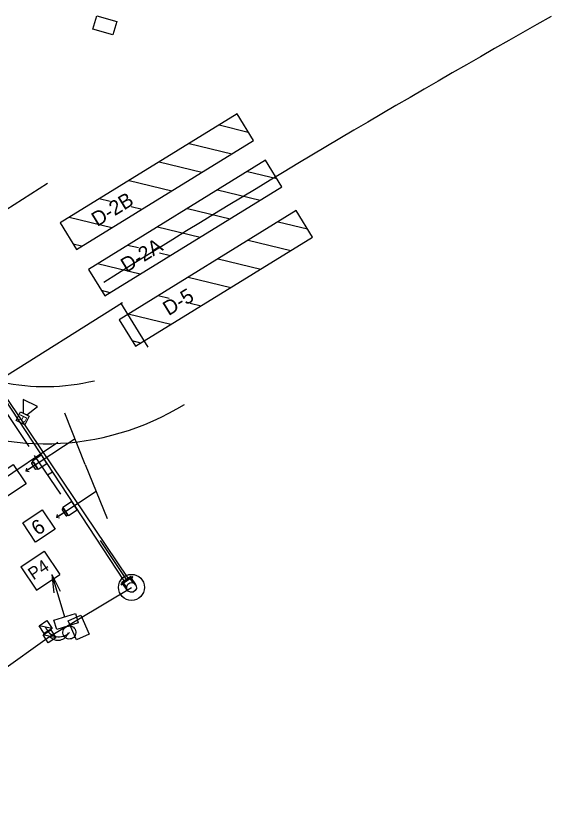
# Model space of a CAD drawing. Extents: x 509004 to 509991, y 882089 to 882397.
# Drawn here: x 509218 to 509321, y 882237.9 to 882390.2 of the extents above; entities that cross this region are included whole.
import ezdxf

# ---------------------------------------------------------------- set-up
doc = ezdxf.new("R2010")
doc.units = 0
for name, color, linetype in [('CLConst_dp', 7, 'Continuous'), ('ConstLines', 7, 'Continuous'), ('TextAlgnCurveData', 7, 'Continuous'), ('TextAlgnStation100', 7, 'Continuous'), ('TextAlgnStation1000', 7, 'Continuous'), ('TextAlgnStation500', 7, 'Continuous'), ('TextAlgnTangent', 7, 'Continuous'), ('TextAlgnTicks1000', 7, 'Continuous'), ('TextAlgnTicks500', 7, 'Continuous'), ('TextAlgnTicks5000', 7, 'Continuous')]:
    doc.layers.add(name, color=color, linetype=linetype)

msp = doc.modelspace()

# ---------------------------------------------------------------- linework, layer by layer
at = {"layer": 'CLConst_dp'}
for p, q in [((509238.84, 882281.59), (509211.35, 882323.35)), ((509239.6, 882282.09), (509211.62, 882323.54)), ((509238.21, 882280.95), (509240.41, 882282.45)), ((509240.09, 882282.42), (509238.35, 882281.26)), ((509240.18, 882282.28), (509238.45, 882281.12)), ((509238.72, 882281.19), (509240, 882282.07)), ((509240.61, 882281.18), (509240, 882282.07)), ((509240.05, 882282), (509240.51, 882282.31)), ((509240.18, 882282.28), (509240.09, 882282.42)), ((509241, 882280.86), (509240.17, 882282.08)), ((509241.05, 882280.89), (509240.22, 882282.11)), ((509240.51, 882282.31), (509240.41, 882282.45)), ((509238.31, 882280.81), (509238.21, 882280.95)), ((509238.31, 882280.81), (509238.77, 882281.12)), ((509238.45, 882281.12), (509238.35, 882281.26)), ((509239.43, 882279.79), (509238.6, 882281.01)), ((509239.48, 882279.82), (509238.65, 882281.04)), ((509239.32, 882280.31), (509238.72, 882281.19)), ((509241.05, 882280.89), (509241, 882280.86)), ((509239.43, 882279.79), (509239.48, 882279.82))]:
    msp.add_line(p, q, dxfattribs=at)
msp.add_lwpolyline([(509239.52, 882280.96), (509239.93, 882281.24), (509240.42, 882281.27), (509240.86, 882281.06), (509241.14, 882280.65), (509241.18, 882280.16), (509240.96, 882279.72), (509240.56, 882279.44), (509240.07, 882279.4), (509239.62, 882279.62), (509239.34, 882280.02), (509239.31, 882280.51)], close=True, dxfattribs=at)
msp.add_circle((509240.24, 882280.35), 2.5, dxfattribs=at)
at = {"layer": 'ConstLines'}
for p, q in [((509224.06, 882358.02), (509191.98, 882337.43)), ((509238.53, 882335.06), (509130.35, 882267.1)), ((509243.47, 882326.52), (509238.21, 882335.06)), ((509220.55, 882307.45), (509215.3, 882315.34)), ((509231.35, 882303.96), (509227.42, 882313.82)), ((509229.38, 882308.89), (509220.24, 882302.89)), ((509121.5, 882237.9), (509226.04, 882308.24)), ((509226.61, 882298.24), (509221.58, 882305.72)), ((509231.35, 882303.96), (509235.58, 882293.58)), ((509224.09, 882301.98), (509225, 882302.59)), ((509233.46, 882298.77), (509226.25, 882294.04))]:
    msp.add_line(p, q, dxfattribs=at)
msp.add_lwpolyline([(509236.65, 882386.57), (509232.81, 882387.67), (509233.54, 882390.24), (509237.39, 882389.13)], close=True, dxfattribs=at)
for centre, radius, start, end in [((510394.49, 880483.77), 2187.81, 119.38433, 122.00756), ((509223.67, 882358.96), 51, 180.6251, 301.6373), ((509223.67, 882358.96), 40, 180.6251, 283.6453)]:
    msp.add_arc(centre, radius, start, end, dxfattribs=at)
at = {"layer": 'TextAlgnCurveData'}
for p, q in [((509224.45, 882270.93), (509240.24, 882280.35)), ((509214.71, 882263.99), (509224.45, 882270.93))]:
    msp.add_line(p, q, dxfattribs=at)
for centre, radius, start, end in [((509226.32, 882273.61), 2.76, 198.7287, 315.3272), ((509226.07, 882272.29), 2.11, 220.2087, 342.3068)]:
    msp.add_arc(centre, radius, start, end, dxfattribs=at)
at = {"layer": 'TextAlgnStation100'}
for p, q in [((509222.47, 882272.98), (509223.97, 882273.97)), ((509223.97, 882273.97), (509224.95, 882272.47)), ((509223.45, 882271.48), (509222.47, 882272.98)), ((509224.95, 882272.47), (509222.47, 882272.98)), ((509224.95, 882272.47), (509223.45, 882271.48)), ((509223.21, 882271.19), (509224.71, 882272.17)), ((509224.19, 882269.69), (509223.21, 882271.19)), ((509225.69, 882270.67), (509223.21, 882271.19)), ((509224.71, 882272.17), (509225.69, 882270.67)), ((509225.69, 882270.67), (509224.19, 882269.69))]:
    msp.add_line(p, q, dxfattribs=at)
at = {"layer": 'TextAlgnStation1000'}
for p, q in [((509221.35, 882304.41), (509222.07, 882303.32)), ((509221.36, 882303.63), (509219.92, 882302.69)), ((509220.05, 882303.28), (509219.92, 882302.69)), ((509221, 882304.18), (509221.72, 882303.09)), ((509221, 882304.18), (509221.72, 882303.09)), ((509220.51, 882302.57), (509219.92, 882302.69)), ((509226.88, 882295.24), (509227.6, 882294.14)), ((509226.88, 882295.24), (509227.6, 882294.14)), ((509227.23, 882295.47), (509227.95, 882294.37)), ((509227.24, 882294.69), (509225.8, 882293.75)), ((509225.93, 882294.34), (509225.8, 882293.75)), ((509226.39, 882293.63), (509225.8, 882293.75))]:
    msp.add_line(p, q, dxfattribs=at)
for points in [[(509222.26, 882303.03), (509221.16, 882304.7), (509222.83, 882305.8), (509223.93, 882304.13)], [(509219.95, 882300.26), (509216.2, 882297.74), (509213.71, 882301.46), (509217.45, 882303.98)], [(509228.14, 882294.09), (509227.04, 882295.76), (509228.71, 882296.85), (509229.81, 882295.18)], [(509225.54, 882291.53), (509221.79, 882289.01), (509219.29, 882292.73), (509223.04, 882295.25)]]:
    msp.add_lwpolyline(points, close=True, dxfattribs=at)
for points in [[(509222.07, 882303.32), (509221.35, 882304.41)], [(509227.95, 882294.37), (509227.23, 882295.47)]]:
    msp.add_lwpolyline(points, dxfattribs=at)
for centre, radius, start, end in [((509221.11, 882304.25), 0.129, 93.9405, 213.2603), ((509221.11, 882304.25), 0.129, 93.9405, 213.2603), ((509220.93, 882306.77), 2.4, 273.9405, 280.0438), ((509220.93, 882306.77), 2.4, 273.9405, 280.0438), ((509221.83, 882303.16), 0.129, 213.2603, 332.5802), ((509221.83, 882303.16), 0.129, 213.2603, 332.5801), ((509224.07, 882301.99), 2.4, 146.4769, 152.5802), ((509224.07, 882301.99), 2.4, 146.4769, 152.5802), ((509226.99, 882295.31), 0.129, 93.9405, 213.2603), ((509226.99, 882295.31), 0.129, 93.9405, 213.2603), ((509226.81, 882297.83), 2.4, 273.9405, 280.0438), ((509226.81, 882297.83), 2.4, 273.9405, 280.0438), ((509227.7, 882294.21), 0.129, 213.2603, 332.5802), ((509227.7, 882294.21), 0.129, 213.2603, 332.5801), ((509229.95, 882293.05), 2.4, 146.4769, 152.5802), ((509229.95, 882293.05), 2.4, 146.4769, 152.5802)]:
    msp.add_arc(centre, radius, start, end, dxfattribs=at)
at = {"layer": 'TextAlgnStation500'}
for p, q in [((509218.96, 882284.32), (509223.44, 882287.33)), ((509223.44, 882287.33), (509226.45, 882282.85)), ((509218.96, 882284.32), (509221.97, 882279.84)), ((509221.97, 882279.84), (509226.45, 882282.85)), ((509224.89, 882282.83), (509227.36, 882274.7)), ((509224.89, 882282.83), (509226.51, 882279.64)), ((509224.89, 882282.83), (509225.32, 882279.27))]:
    msp.add_line(p, q, dxfattribs=at)
at = {"layer": 'TextAlgnTicks1000'}
for p, q in [((509260.56, 882371.4), (509226.5, 882350.42)), ((509263.71, 882366.29), (509260.56, 882371.4)), ((509257.09, 882369.26), (509262.72, 882367.89)), ((509229.65, 882345.31), (509263.71, 882366.29)), ((509251.31, 882365.7), (509259.52, 882363.71)), ((509266.02, 882362.47), (509231.96, 882341.49)), ((509269.16, 882357.36), (509266.02, 882362.47)), ((509245.54, 882362.15), (509253.75, 882360.16)), ((509262.54, 882360.33), (509268.18, 882358.96)), ((509239.77, 882358.59), (509247.98, 882356.6)), ((509235.11, 882336.38), (509269.16, 882357.36)), ((509256.77, 882356.77), (509264.98, 882354.78)), ((509236.14, 882354.53), (509234, 882355.04)), ((509240.17, 882353.57), (509242.27, 882353.08)), ((509251, 882353.22), (509259.21, 882351.23)), ((509271.93, 882352.79), (509237.87, 882331.81)), ((509275.08, 882347.68), (509271.93, 882352.79)), ((509226.5, 882350.42), (509229.65, 882345.31)), ((509236.45, 882349.5), (509228.23, 882351.48)), ((509268.46, 882350.65), (509274.09, 882349.29)), ((509245.23, 882349.66), (509253.44, 882347.67)), ((509241.02, 882326.7), (509275.08, 882347.68)), ((509262.68, 882347.1), (509270.89, 882345.11)), ((509230.64, 882345.92), (509229.02, 882346.33)), ((509241.6, 882345.6), (509239.46, 882346.11)), ((509245.63, 882344.64), (509247.72, 882344.15)), ((509241.9, 882340.57), (509233.69, 882342.55)), ((509256.91, 882343.54), (509265.12, 882341.55)), ((509231.96, 882341.49), (509235.11, 882336.38)), ((509251.14, 882339.99), (509259.35, 882338)), ((509236.1, 882336.99), (509234.48, 882337.4)), ((509247.51, 882335.92), (509245.37, 882336.43)), ((509251.54, 882334.96), (509253.64, 882334.48)), ((509237.87, 882331.81), (509241.02, 882326.7)), ((509247.82, 882330.89), (509239.6, 882332.88)), ((509242.01, 882327.32), (509240.39, 882327.73)), ((509219.37, 882313.85), (509220.07, 882313.5))]:
    msp.add_line(p, q, dxfattribs=at)
msp.add_lwpolyline([(509220.07, 882313.5), (509222.16, 882315.1), (509219.37, 882316.47), (509219.37, 882313.85)], dxfattribs=at)
msp.add_lwpolyline([(509220.55, 882313.26), (509219.72, 882311.57), (509218.05, 882312.4), (509218.88, 882314.09)], close=True, dxfattribs=at)
at = {"layer": 'TextAlgnTicks500'}
for p, q in [((509225.28, 882274.07), (509229.44, 882275.33)), ((509225.84, 882272.24), (509225.28, 882274.07)), ((509229.44, 882275.33), (509229.99, 882273.5)), ((509229.99, 882273.5), (509225.84, 882272.24))]:
    msp.add_line(p, q, dxfattribs=at)
msp.add_lwpolyline([(509230.48, 882275.03), (509232.1, 882271.37), (509229.67, 882270.29), (509228.04, 882273.94)], close=True, dxfattribs=at)
msp.add_ellipse((509228.28, 882271.67), major_axis=(-1.09, -0.62), ratio=0.999996, dxfattribs=at)
at = {"layer": 'TextAlgnTicks5000'}
msp.add_line((509234.22, 882289.33), (509239.22, 882281.84), dxfattribs=at)

# ---------------------------------------------------------------- texts
at = {"layer": 'TextAlgnStation1000'}
msp.add_text('6', height=2.8, rotation=33.9138, dxfattribs=at).set_placement((509222.16, 882290.21))
at = {"layer": 'TextAlgnStation500'}
msp.add_text('P4', height=2.399, rotation=33.9138, dxfattribs=at).set_placement((509221.35, 882281.66))
at = {"layer": 'TextAlgnTangent'}
for s, p in [('D-2B', (509233.64, 882349.63)), ('D-2A', (509239.26, 882340.8)), ('D-5', (509247.38, 882332.48))]:
    msp.add_text(s, height=2.8, rotation=31.6339, dxfattribs=at).set_placement(p)
at = {"layer": 'TextAlgnTicks1000'}
msp.add_text('R', height=1.49, rotation=243.6733, dxfattribs=at).set_placement((509218.92, 882313.75))

doc.saveas('drawing.dxf')
